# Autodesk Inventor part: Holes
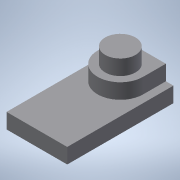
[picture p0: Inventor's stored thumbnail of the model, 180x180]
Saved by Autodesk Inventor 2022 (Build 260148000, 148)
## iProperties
Created: 2013-12
Part Number: Holes
Material: Generic
Document SubType Name: Modeling
Designer: John
Density: 1 g/cm^3
Appearance: Default
Author: John
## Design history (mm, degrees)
sketch "Sketch1"
  geometry: L1 (0, 0)-(-50.8, 0); L2 (-50.8, 0)-(-50.8, -88.9); L3 (-50.8, -88.9)-(0, -88.9); L4 (0, -88.9)-(0, 0)
  constraints: 8 end point, 2 parallel, 1 horizontal, 1 perpendicular
  dimensions: "d0" = 50.8 distance of L3.end L2.end; "d1" = 88.9 distance of L2.end L1.end
extrude "Extrusion1" new body sketch "Sketch1" distance "d2" = 12.7; taper "d3" = 0 deg
sketch "Sketch2"
  geometry: L1 (50.8, 0)-(50.8, 88.9) reference; L2 (50.8, 88.9)-(0, 88.9) reference; L3 (0, 88.9)-(0, 0) reference; L4 (6.35, 88.9)-(44.45, 88.9); L5 (44.45, 88.9)-(44.45, 69.85); L6 (44.45, 69.85)-(6.35, 69.85); L7 (6.35, 69.85)-(6.35, 88.9); L8 (6.35, 79.375)-(0, 79.375); L9 (44.45, 79.375)-(50.8, 79.375); 1 further point
  constraints: 12 end point, 3 midpoint, 3 perpendicular, 3 point on line, 2 parallel, 1 collinear, 1 horizontal, 1 horizontal alignment, 2 other
  dimensions: "d4" = 19.05 distance of L4.end L5.end; "d5" = 6.35 distance between parallel lines of L3 L7
extrude "Extrusion2" join sketch "Sketch2" distance "d6" = 12.7; taper "d7" = 0 deg
sketch "Sketch3"
  geometry: C1 r 12.7 at (25.4, 69.85); A1 r 19.05 centre (25.4, 69.85) between (6.35, 69.85) and (44.45, 69.85) reference; 1 further point
  constraints: 1 centre point, 1 coincident
  dimensions: "d8" = 25.4 diameter of C1
extrude "Extrusion3" join sketch "Sketch3" distance "d9" = 12.7; taper "d10" = 0 deg
sketch "Sketch6"
  geometry: L1 (44.45, 88.9)-(44.45, 69.85) reference; L2 (6.35, 69.85)-(6.35, 88.9) reference; L3 (6.35, 88.9)-(0, 88.9) reference; L4 (0, 88.9)-(0, 0) reference; L5 (0, 0)-(50.8, 0) reference; L6 (50.8, 0)-(50.8, 88.9) reference; L7 (50.8, 88.9)-(44.45, 88.9) reference; L8 (44.45, 88.9)-(44.45, 6.35); L9 (44.45, 6.35)-(6.35, 6.35); L10 (6.35, 6.35)-(6.35, 88.9); L11 (6.35, 38.1)-(44.45, 38.1); A1 r 19.05 centre (25.4, 69.85) between (6.35, 69.85) and (44.45, 69.85) reference
  constraints: 8 end point, 2 point on line, 1 perpendicular, 2 other
  dimensions: "d35" = 6.35 distance between parallel lines of L5 L9; "d36" = 31.75 distance between parallel lines of L9 L11
body "Solid1"
